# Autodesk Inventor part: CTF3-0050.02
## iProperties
Shininess: 64.0
Length Units: 11269
Angle Units: 11279
Time Units: 11290
Mass Units: 11283
Length Display Precision: 3
Angle Display Precision: 2
Compacted: True
Part Number: CTF3-0050.02
Document SubType Name: Modeling
Created: 2003-11
Designer: Lollo
Density: 0.0
Volumn: 0.0
Area: 0.0
PropertySet Name: Model Information
Control State: 0
Master: False
Checked Out: False
Author: Lollo
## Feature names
1. Estrusione1 [Extrusion]
2. Estrusione2 [Extrusion]
3. Estrusione3 [Extrusion]
4. Smusso2 [Chamfer]
5. Smusso4 [Chamfer]
6. Smusso6 [Chamfer]
7. Smusso8 [Chamfer]
8. Smusso9 [Chamfer]
9. Smusso10 [Chamfer]
10. Smusso11 [Chamfer]
11. Smusso12 [Chamfer]
12. Smusso13 [Chamfer]
